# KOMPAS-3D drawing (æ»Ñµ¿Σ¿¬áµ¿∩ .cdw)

Referenced files: Спецификация 1.cdw
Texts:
  Опора  подшипниковая  Спецификация
  Текст на чертеже
  Размерные надписи
  Шероховатость
  Линия-выноска #1
  Линия-выноска #2
  Линия-выноска #3
  Отклонения формы и база
  Заголовок таблицы
  Ячейка таблицы
  Стрелка вида
  Обозначение изменения
  Фигурная скобка
  Номер узла
  Марка координационной оси
  VRCB
  Выносная надпись
  Обозначение узла
  Марка/позиционное обозначение с линией-выноской
  Марка/позиционное обозначение на линии
  Марка/позиционное обозначение без линии-выноски
  ХХХХ.ХХ.ХХ.00 СБ
  Документация
  Детали
  Корпус
  Крышка
  Вкладыш верхний
  Вкладыш нижний
  Стандартные изделия
  Опора
  подшипниковая
  Сборочный чертеж
  Вкладыш
  ГОСТ 1477-93
  Гайка М12.5
  ГОСТ 5915-70
  Гайка М16.5 ГОСТ 5915-70
  Шпилька М12х30 12 22 58
  Шпилька М16х40 16 30 58
  Штифт 12Гх15
  ГОСТ 3128-70
Dimensions and other numbers on the sheet: 7; 4; 1:1; 1; 2; 3; 5; 6; 8; 9; 10; 11; 12; 0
